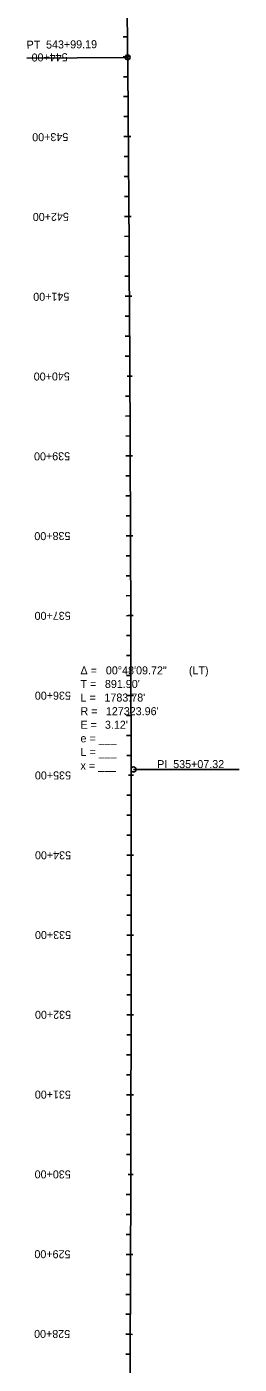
# Model space of a CAD drawing. Extents: x 23417911 to 23421158, y 6737892 to 6791804.
# Drawn here: x 23420763 to 23421028, y 6778333 to 6780008 of the extents above; entities that cross this region are included whole.
import ezdxf

# ---------------------------------------------------------------- set-up
doc = ezdxf.new("R2010")
doc.units = 0
for name, color, linetype in [('Alignment', 7, 'Continuous'), ('TextAlignment', 7, 'Continuous'), ('TextAlignmentLrg', 7, 'Continuous'), ('TextAlignmentSml', 7, 'Continuous')]:
    doc.layers.add(name, color=color, linetype=linetype)

msp = doc.modelspace()

# ---------------------------------------------------------------- linework, layer by layer
at = {"layer": 'Alignment'}
msp.add_line((23420888.7, 6779969.4), (23420840.8, 6785772.8), dxfattribs=at)
msp.add_line((23420888.7, 6779969.4), (23420840.8, 6785772.8), dxfattribs=at)
msp.add_arc((23293569.1, 6778919.3), 127324, 359.669872, 0.472573, dxfattribs=at)
msp.add_arc((23293569.1, 6778919.3), 127324, 359.669872, 0.472573, dxfattribs=at)
at = {"layer": 'TextAlignment'}
for p, q in [((23420888.7, 6779969.4), (23420762.7, 6779968.4)), ((23420762.7, 6779968.4), (23420762.7, 6779968.4)), ((23420896.1, 6779077.6), (23421028.1, 6779077.7)), ((23421028.1, 6779077.7), (23421028.1, 6779077.7))]:
    msp.add_line(p, q, dxfattribs=at)
for centre in [(23420888.7, 6779969.4), (23420896.1, 6779077.6)]:
    msp.add_circle(centre, 3.12, dxfattribs=at)
at = {"layer": 'TextAlignmentLrg'}
for p, q in [((23420888.7, 6779970.2), (23420883.2, 6779970.2)), ((23420889.5, 6779870.3), (23420884, 6779870.2)), ((23420890.2, 6779770.3), (23420884.7, 6779770.2)), ((23420890.8, 6779670.3), (23420885.4, 6779670.2)), ((23420888.3, 6779570.2), (23420894.4, 6779570.3)), ((23420891.8, 6779470.3), (23420886.4, 6779470.2)), ((23420892.2, 6779370.3), (23420886.8, 6779370.2)), ((23420892.6, 6779270.3), (23420887.1, 6779270.2)), ((23420892.8, 6779170.3), (23420887.3, 6779170.3)), ((23420889.9, 6779070.3), (23420896, 6779070.3)), ((23420893, 6778970.3), (23420887.6, 6778970.3)), ((23420893, 6778870.3), (23420887.6, 6778870.3)), ((23420893, 6778770.3), (23420887.5, 6778770.3)), ((23420892.8, 6778670.3), (23420887.3, 6778670.3)), ((23420889.5, 6778570.3), (23420895.6, 6778570.3)), ((23420892.2, 6778470.3), (23420886.8, 6778470.3)), ((23420891.9, 6778370.3), (23420886.4, 6778370.3))]:
    msp.add_line(p, q, dxfattribs=at)
at = {"layer": 'TextAlignmentSml'}
for p, q in [((23420888.5, 6779995.2), (23420883, 6779995.2)), ((23420885.6, 6779970.2), (23420891.8, 6779970.3)), ((23420888.9, 6779945.2), (23420883.4, 6779945.2)), ((23420889.1, 6779920.3), (23420883.6, 6779920.2)), ((23420889.3, 6779895.3), (23420883.8, 6779895.2)), ((23420886.4, 6779870.2), (23420892.5, 6779870.3)), ((23420889.7, 6779845.3), (23420884.2, 6779845.2)), ((23420889.9, 6779820.3), (23420884.4, 6779820.2)), ((23420890, 6779795.3), (23420884.6, 6779795.2)), ((23420887.1, 6779770.2), (23420893.3, 6779770.3)), ((23420890.4, 6779745.3), (23420884.9, 6779745.2)), ((23420890.5, 6779720.3), (23420885.1, 6779720.2)), ((23420890.7, 6779695.3), (23420885.2, 6779695.2)), ((23420887.8, 6779670.2), (23420893.9, 6779670.3)), ((23420891, 6779645.3), (23420885.5, 6779645.2)), ((23420891.1, 6779620.3), (23420885.7, 6779620.2)), ((23420891.2, 6779595.3), (23420885.8, 6779595.2)), ((23420888.3, 6779570.2), (23420894.4, 6779570.3)), ((23420891.5, 6779545.3), (23420886, 6779545.2)), ((23420891.6, 6779520.3), (23420886.2, 6779520.2)), ((23420891.7, 6779495.3), (23420886.3, 6779495.2)), ((23420888.8, 6779470.2), (23420894.9, 6779470.3)), ((23420892, 6779445.3), (23420886.5, 6779445.2)), ((23420892.1, 6779420.3), (23420886.6, 6779420.2)), ((23420892.2, 6779395.3), (23420886.7, 6779395.2)), ((23420889.2, 6779370.2), (23420895.3, 6779370.3)), ((23420892.3, 6779345.3), (23420886.9, 6779345.2)), ((23420892.4, 6779320.3), (23420886.9, 6779320.2)), ((23420892.5, 6779295.3), (23420887, 6779295.2)), ((23420889.5, 6779270.3), (23420895.6, 6779270.3)), ((23420892.6, 6779245.3), (23420887.2, 6779245.2)), ((23420892.7, 6779220.3), (23420887.2, 6779220.2)), ((23420892.7, 6779195.3), (23420887.3, 6779195.2)), ((23420889.7, 6779170.3), (23420895.9, 6779170.3)), ((23420892.8, 6779145.3), (23420887.4, 6779145.3)), ((23420892.9, 6779120.3), (23420887.4, 6779120.3)), ((23420892.9, 6779095.3), (23420887.5, 6779095.3)), ((23420889.9, 6779070.3), (23420896, 6779070.3)), ((23420893, 6779045.3), (23420887.5, 6779045.3)), ((23420893, 6779020.3), (23420887.5, 6779020.3)), ((23420893, 6778995.3), (23420887.6, 6778995.3)), ((23420890, 6778970.3), (23420896.1, 6778970.3)), ((23420893, 6778945.3), (23420887.6, 6778945.3)), ((23420893, 6778920.3), (23420887.6, 6778920.3)), ((23420893, 6778895.3), (23420887.6, 6778895.3)), ((23420890, 6778870.3), (23420896.1, 6778870.3)), ((23420893, 6778845.3), (23420887.6, 6778845.3)), ((23420893, 6778820.3), (23420887.5, 6778820.3)), ((23420893, 6778795.3), (23420887.5, 6778795.3)), ((23420889.9, 6778770.3), (23420896, 6778770.3)), ((23420892.9, 6778745.3), (23420887.5, 6778745.3)), ((23420892.9, 6778720.3), (23420887.4, 6778720.3)), ((23420892.8, 6778695.3), (23420887.4, 6778695.3)), ((23420889.7, 6778670.3), (23420895.9, 6778670.3)), ((23420892.7, 6778645.3), (23420887.3, 6778645.3)), ((23420892.7, 6778620.3), (23420887.2, 6778620.3)), ((23420892.6, 6778595.3), (23420887.2, 6778595.3)), ((23420889.5, 6778570.3), (23420895.6, 6778570.3)), ((23420892.5, 6778545.3), (23420887, 6778545.3)), ((23420892.4, 6778520.3), (23420887, 6778520.3)), ((23420892.3, 6778495.3), (23420886.9, 6778495.3)), ((23420889.2, 6778470.3), (23420895.3, 6778470.3)), ((23420892.2, 6778445.3), (23420886.7, 6778445.3)), ((23420892.1, 6778420.3), (23420886.6, 6778420.3)), ((23420892, 6778395.3), (23420886.5, 6778395.3)), ((23420888.8, 6778370.3), (23420894.9, 6778370.2)), ((23420891.7, 6778345.3), (23420886.3, 6778345.3))]:
    msp.add_line(p, q, dxfattribs=at)

# ---------------------------------------------------------------- texts
at = {"layer": 'TextAlignment'}
for s, rotation, p in [('PT', 0.4726, (23420762.5, 6779980.2)), ('543+99.19', 0.4726, (23420786.8, 6779980.4)), ('535+07.32', 0.0712, (23420945.6, 6779079.3)), ('PI ', 0.0712, (23420925.6, 6779079.3))]:
    msp.add_text(s, height=10.02, rotation=rotation, dxfattribs=at).set_placement(p)
for s, p in [('00°48\'09.72"', (23420861.5, 6779196.7)), (' (LT)', (23420961.5, 6779196.7)), ('Δ = ', (23420829.8, 6779196.7)), ('T = ', (23420829.8, 6779179.7)), ("891.90'", (23420860.3, 6779179.7)), ('L = ', (23420829.8, 6779162.7)), ("1783.78'", (23420859.7, 6779162.7)), ('R = ', (23420829.8, 6779145.6)), ("127323.96'", (23420861.5, 6779145.6)), ('E = ', (23420829.8, 6779128.6)), ("3.12'", (23420860.3, 6779128.6)), ('e = ___ ', (23420829.8, 6779111.6)), ('L = ___', (23420829.8, 6779094.5)), ('x = ___', (23420829.8, 6779077.5))]:
    msp.add_text(s, height=10.02, dxfattribs=at).set_placement(p)
at = {"layer": 'TextAlignmentLrg'}
for s, rotation, p in [('540+00', 180.2929, (23420816.4, 6779574.9)), ('535+00', 180.0679, (23420817.9, 6779075.2)), ('530+00', 179.8429, (23420817.6, 6778575.5))]:
    msp.add_text(s, height=10.02, rotation=rotation, dxfattribs=at).set_placement(p)
at = {"layer": 'TextAlignmentSml'}
for s, rotation, p in [('544+00', 180.4726, (23420813.7, 6779974.6)), ('543+00', 180.4279, (23420814.5, 6779874.7)), ('542+00', 180.3829, (23420815.2, 6779774.8)), ('541+00', 180.3379, (23420815.8, 6779674.8)), ('540+00', 180.2929, (23420816.4, 6779574.9)), ('539+00', 180.2479, (23420816.8, 6779474.9)), ('538+00', 180.2029, (23420817.2, 6779375)), ('537+00', 180.1579, (23420817.5, 6779275.1)), ('536+00', 180.1129, (23420817.8, 6779175.1)), ('535+00', 180.0679, (23420817.9, 6779075.2)), ('534+00', 180.0229, (23420818, 6778975.2)), ('533+00', 179.9779, (23420818, 6778875.3)), ('532+00', 179.9329, (23420818, 6778775.4)), ('531+00', 179.8879, (23420817.8, 6778675.4)), ('530+00', 179.8429, (23420817.6, 6778575.5)), ('529+00', 179.7979, (23420817.3, 6778475.5)), ('528+00', 179.7529, (23420816.9, 6778375.6))]:
    msp.add_text(s, height=10.02, rotation=rotation, dxfattribs=at).set_placement(p)

doc.saveas('drawing.dxf')
